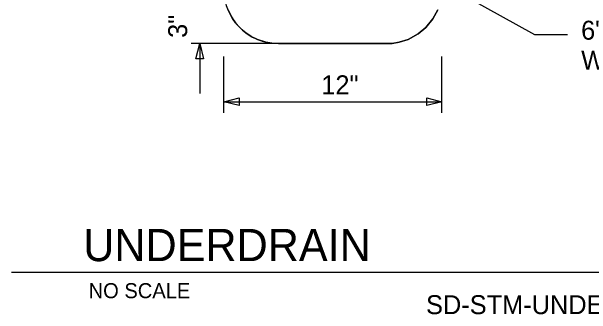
# Model space of a CAD drawing. Extents: x 10378.8 to 10426.8, y 9885.5 to 9932.9.
# Drawn here: x 10378.83 to 10410.75, y 9885.55 to 9902.24 of the extents above; entities that cross this region are included whole.
import ezdxf

# ---------------------------------------------------------------- set-up
doc = ezdxf.new("R2010")
doc.units = 0
for name, color, linetype in [('Default', 7, 'Continuous'), ('G-ANNO-TEXT', 7, 'Continuous'), ('G-ANNO-TTXT', 7, 'Continuous'), ('G-DETL-OTLN', 7, 'Continuous'), ('G-DETL-PATT', 7, 'Continuous')]:
    doc.layers.add(name, color=color, linetype=linetype)

# ---------------------------------------------------------------- blocks, each defined once
blk = doc.blocks.new('TERARR')
at = {"layer": 'Default'}
blk.add_lwpolyline([(-0.667, 0.167), (0, 0), (-0.667, -0.167)], close=True, dxfattribs=at)

msp = doc.modelspace()

# ---------------------------------------------------------------- linework, layer by layer
at = {"layer": 'G-ANNO-TEXT'}
for p, q in [((10393.518, 9900.473), (10388.709, 9900.473)), ((10389.187, 9900.473), (10389.187, 9897.726)), ((10390.518, 9896.649), (10390.518, 9899.761)), ((10402.518, 9896.649), (10402.518, 9899.762)), ((10390.518, 9897.266), (10402.518, 9897.266)), ((10378.83, 9887.877), (10413.599, 9887.877))]:
    msp.add_line(p, q, dxfattribs=at)
msp.add_lwpolyline([(10399.518, 9905.473), (10407.611, 9900.969), (10409.439, 9900.969)], dxfattribs=at)
at = {"layer": 'G-DETL-OTLN'}
msp.add_line((10393.518, 9900.473), (10399.518, 9900.473), dxfattribs=at)
msp.add_lwpolyline([(10402.29, 9902.325), (10402.025, 9901.839), (10401.639, 9901.352), (10401.221, 9901.008), (10400.666, 9900.701), (10400.177, 9900.543), (10399.778, 9900.472), (10399.518, 9900.473), (10393.518, 9900.473), (10393.151, 9900.497), (10392.835, 9900.552), (10392.419, 9900.677), (10392.37, 9900.701), (10392.028, 9900.871), (10391.735, 9901.059), (10391.547, 9901.211), (10391.397, 9901.352), (10391.167, 9901.613), (10390.988, 9901.861), (10390.837, 9902.124), (10390.746, 9902.325)], dxfattribs=at)
msp.add_arc((10393.518, 9903.473), 3, 180, 270, dxfattribs=at)
at = {"layer": 'G-DETL-PATT'}
msp.add_lwpolyline([(10390.746, 9902.325), (10390.837, 9902.124), (10390.988, 9901.861), (10391.167, 9901.613), (10391.397, 9901.352), (10391.547, 9901.211), (10391.735, 9901.059), (10392.028, 9900.871), (10392.37, 9900.701), (10392.419, 9900.677), (10392.835, 9900.552), (10393.151, 9900.497), (10393.518, 9900.473), (10399.518, 9900.473), (10399.778, 9900.472), (10400.177, 9900.543), (10400.666, 9900.701), (10401.221, 9901.008), (10401.639, 9901.352), (10402.025, 9901.839), (10402.29, 9902.325)], dxfattribs=at)

# ---------------------------------------------------------------- block references
at = {"layer": 'G-ANNO-TEXT', "xscale": 1.24992, "yscale": 1.24992}
for p, rotation in [((10389.187, 9900.473), 90), ((10390.518, 9897.266), 180)]:
    msp.add_blockref('TERARR', p, dxfattribs=dict(at, rotation=rotation))
msp.add_blockref('TERARR', (10402.518, 9897.266), dxfattribs=at)

# ---------------------------------------------------------------- texts
at = {"layer": 'G-ANNO-TEXT'}
msp.add_text('3"', height=1.044, rotation=90, dxfattribs=at).set_placement((10388.496, 9900.788))
for s, height, p in [('6" HDPE PERFORATED ', 1.044, (10410.187, 9900.689)), ('WRAPPED UNDERDRAIN', 1.044, (10410.187, 9899.045)), ('12"', 1.044, (10395.882, 9897.679)), ('NO SCALE', 0.828, (10383.071, 9886.442)), ('SD-STM-UNDERDRAIN', 1.044, (10401.649, 9885.562))]:
    msp.add_text(s, height=height, dxfattribs=at).set_placement(p)
at = {"layer": 'G-ANNO-TTXT'}
msp.add_text('UNDERDRAIN ', height=1.776, dxfattribs=at).set_placement((10382.774, 9888.483))

doc.saveas('drawing.dxf')
